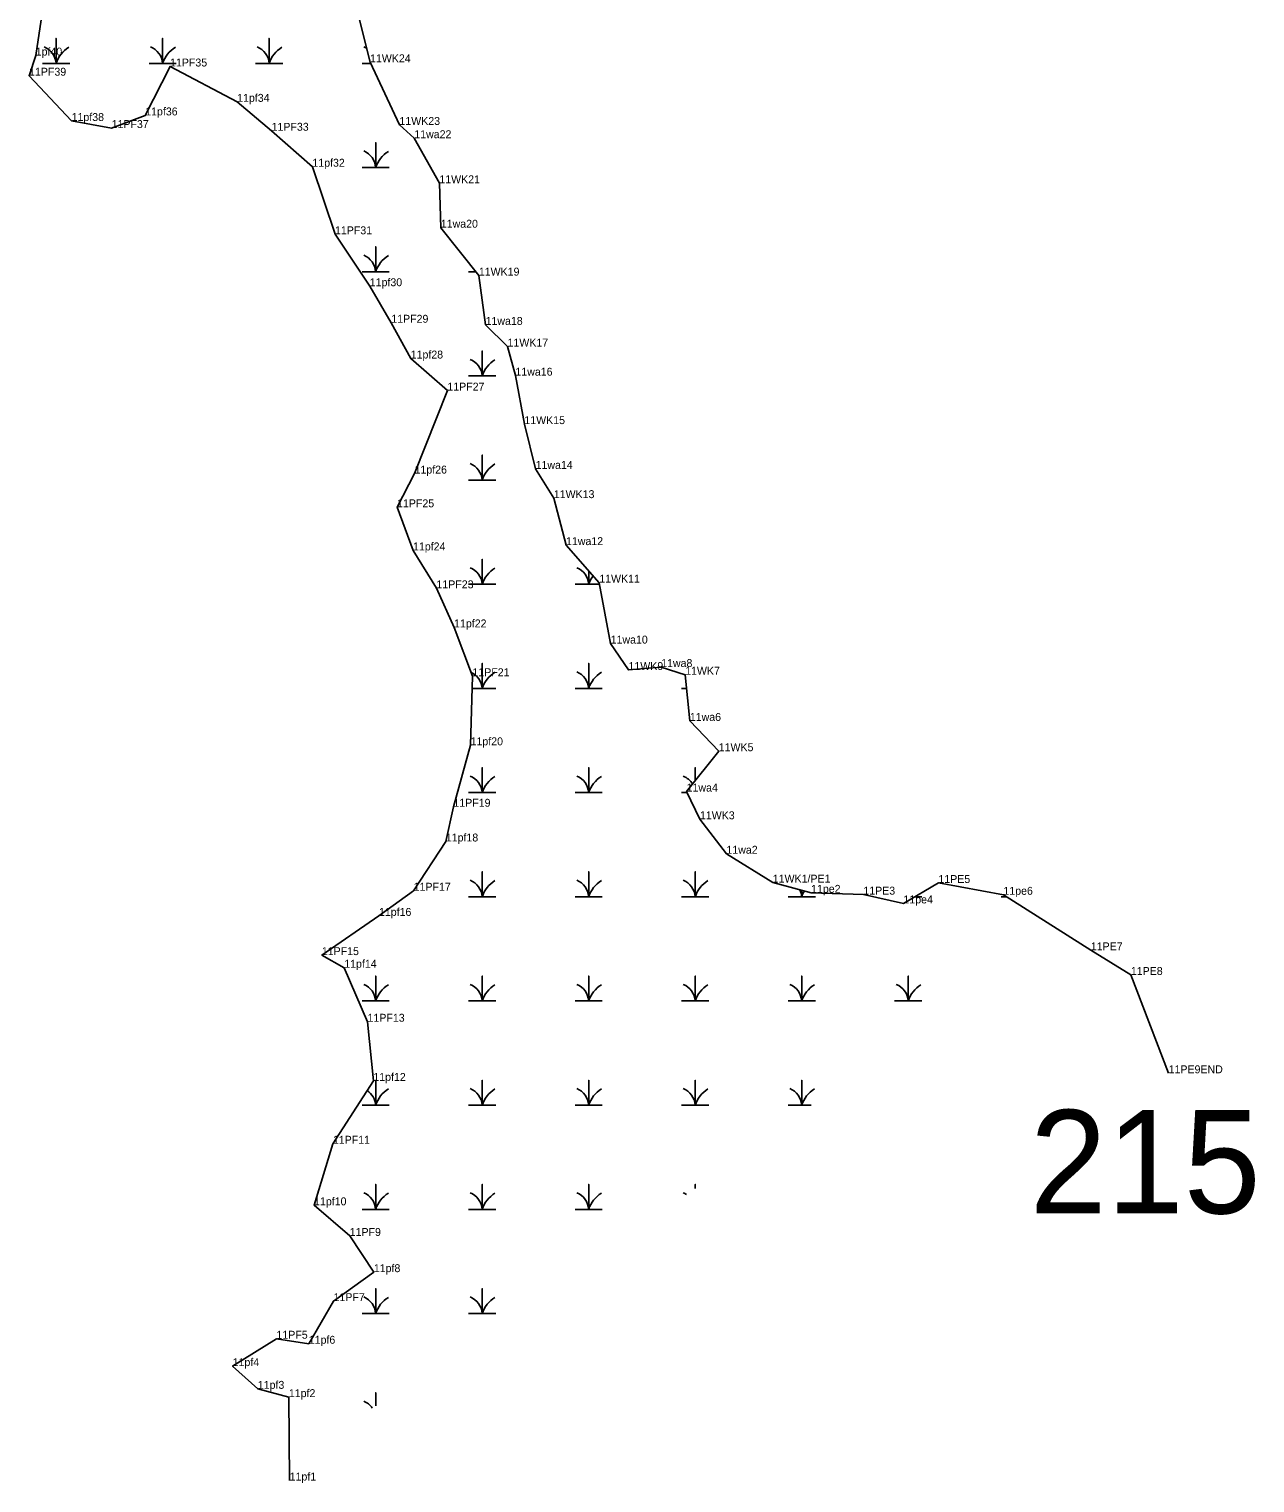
# Model space of a CAD drawing. Extents: x 2072529 to 2268796, y 436423 to 470397.
# Drawn here: x 2234819 to 2235593, y 448079 to 448997 of the extents above; entities that cross this region are included whole.
import ezdxf

# ---------------------------------------------------------------- set-up
doc = ezdxf.new("R2010")
doc.units = 0
for name, color, linetype in [('Default', 7, 'Continuous'), ('Exist Environmental Wetland Boundary', 7, 'Continuous'), ('Exist Environmental Wetland Boundary Cogo Comment', 7, 'Continuous'), ('Exist Environmental Wetland Boundary Cogo Point CELL', 7, 'Continuous'), ('Exist Hydro Swamp or Marsh', 7, 'Continuous')]:
    doc.layers.add(name, color=color, linetype=linetype)

msp = doc.modelspace()

# ---------------------------------------------------------------- linework, layer by layer
at = {"layer": 'Exist Environmental Wetland Boundary'}
for points in [[(2235024.3, 449016.68), (2235034.29, 448976.24)], [(2234983.52, 448080.45), (2234983.04, 448133.13), (2234963.42, 448138.38), (2234947.54, 448152.71), (2234975.2, 448170.02), (2234995.61, 448166.86), (2235011.24, 448193.78), (2235036.68, 448212.07), (2235021.44, 448234.93), (2234998.95, 448254.29), (2235010.83, 448293.18), (2235036.36, 448332.86), (2235032.71, 448370.24), (2235017.99, 448404.35), (2235003.85, 448412.32), (2235039.92, 448437.08), (2235061.81, 448452.98), (2235082.13, 448484.09), (2235086.92, 448506.04), (2235097.77, 448544.83), (2235098.94, 448588.49), (2235087.36, 448619.32), (2235076.21, 448644.01), (2235061.42, 448667.94), (2235051.35, 448695.16), (2235062.4, 448716.48), (2235083.09, 448768.88), (2235059.95, 448789.14), (2235047.7, 448811.73), (2235034.11, 448834.81), (2235012.16, 448867.6), (2234997.88, 448910.29), (2234972.11, 448933), (2234950.38, 448951.27), (2234908.02, 448973.6), (2234892.34, 448942.69), (2234871.13, 448934.72), (2234845.86, 448939.16), (2234819.01, 448967.79), (2234823.2, 448980.5), (2234826.7, 449003.12)], [(2235034.29, 448976.24), (2235052.84, 448936.68), (2235062.23, 448928.31), (2235078.04, 448899.81), (2235078.97, 448871.77), (2235102.97, 448841.5), (2235107.23, 448810.38), (2235121.09, 448796.7), (2235126.08, 448778.31), (2235131.73, 448747.72), (2235138.81, 448719.4), (2235150.32, 448700.95), (2235158.01, 448671.28), (2235179.01, 448647.56), (2235186.19, 448609.09), (2235197.46, 448592.4), (2235218.09, 448594.26), (2235233.25, 448589.41), (2235236.19, 448560.23), (2235254.42, 448541.12), (2235234.17, 448515.62), (2235242.57, 448498.12), (2235259.31, 448476.34), (2235288.56, 448458.11), (2235312.75, 448451.67), (2235345.74, 448450.52), (2235371.06, 448444.98), (2235393.14, 448457.87), (2235434.17, 448450.43), (2235489.36, 448415.34), (2235514.65, 448399.78), (2235538.49, 448337.67)]]:
    msp.add_lwpolyline(points, dxfattribs=at)
at = {"layer": 'Exist Environmental Wetland Boundary Cogo Point CELL'}
for p, q in [((2234823.2, 448980.5), (2234823.2, 448980.5)), ((2235034.29, 448976.24), (2235034.29, 448976.24)), ((2234819.01, 448967.79), (2234819.01, 448967.79)), ((2234908.02, 448973.6), (2234908.02, 448973.6)), ((2234950.38, 448951.27), (2234950.38, 448951.27)), ((2234845.86, 448939.16), (2234845.86, 448939.16)), ((2234892.34, 448942.69), (2234892.34, 448942.69)), ((2234871.13, 448934.72), (2234871.13, 448934.72)), ((2234972.11, 448933), (2234972.11, 448933)), ((2235052.84, 448936.68), (2235052.84, 448936.68)), ((2235062.23, 448928.31), (2235062.23, 448928.31)), ((2234997.88, 448910.29), (2234997.88, 448910.29)), ((2235078.04, 448899.81), (2235078.04, 448899.81)), ((2235012.16, 448867.6), (2235012.16, 448867.6)), ((2235078.97, 448871.77), (2235078.97, 448871.77)), ((2235102.97, 448841.5), (2235102.97, 448841.5)), ((2235034.11, 448834.81), (2235034.11, 448834.81)), ((2235047.7, 448811.73), (2235047.7, 448811.73)), ((2235107.23, 448810.38), (2235107.23, 448810.38)), ((2235121.09, 448796.7), (2235121.09, 448796.7)), ((2235059.95, 448789.14), (2235059.95, 448789.14)), ((2235126.08, 448778.31), (2235126.08, 448778.31)), ((2235083.09, 448768.88), (2235083.09, 448768.88)), ((2235131.73, 448747.72), (2235131.73, 448747.72)), ((2235138.81, 448719.4), (2235138.81, 448719.4)), ((2235062.4, 448716.48), (2235062.4, 448716.48)), ((2235150.32, 448700.95), (2235150.32, 448700.95)), ((2235051.35, 448695.16), (2235051.35, 448695.16)), ((2235061.42, 448667.94), (2235061.42, 448667.94)), ((2235158.01, 448671.28), (2235158.01, 448671.28)), ((2235076.21, 448644.01), (2235076.21, 448644.01)), ((2235179.01, 448647.56), (2235179.01, 448647.56)), ((2235087.36, 448619.32), (2235087.36, 448619.32)), ((2235186.19, 448609.09), (2235186.19, 448609.09)), ((2235197.46, 448592.4), (2235197.46, 448592.4)), ((2235218.09, 448594.26), (2235218.09, 448594.26)), ((2235233.25, 448589.41), (2235233.25, 448589.41)), ((2235098.94, 448588.49), (2235098.94, 448588.49)), ((2235236.19, 448560.23), (2235236.19, 448560.23)), ((2235097.77, 448544.83), (2235097.77, 448544.83)), ((2235254.42, 448541.12), (2235254.42, 448541.12)), ((2235234.17, 448515.62), (2235234.17, 448515.62)), ((2235086.92, 448506.04), (2235086.92, 448506.04)), ((2235242.57, 448498.12), (2235242.57, 448498.12)), ((2235082.13, 448484.09), (2235082.13, 448484.09)), ((2235259.31, 448476.34), (2235259.31, 448476.34)), ((2235061.81, 448452.98), (2235061.81, 448452.98)), ((2235288.56, 448458.11), (2235288.56, 448458.11)), ((2235312.75, 448451.67), (2235312.75, 448451.67)), ((2235393.14, 448457.87), (2235393.14, 448457.87)), ((2235345.74, 448450.52), (2235345.74, 448450.52)), ((2235371.06, 448444.98), (2235371.06, 448444.98)), ((2235434.17, 448450.43), (2235434.17, 448450.43)), ((2235039.92, 448437.08), (2235039.92, 448437.08)), ((2235489.36, 448415.34), (2235489.36, 448415.34)), ((2235003.85, 448412.32), (2235003.85, 448412.32)), ((2235017.99, 448404.35), (2235017.99, 448404.35)), ((2235514.65, 448399.78), (2235514.65, 448399.78)), ((2235032.71, 448370.24), (2235032.71, 448370.24)), ((2235036.36, 448332.86), (2235036.36, 448332.86)), ((2235538.49, 448337.67), (2235538.49, 448337.67)), ((2235010.83, 448293.18), (2235010.83, 448293.18)), ((2234998.95, 448254.29), (2234998.95, 448254.29)), ((2235021.44, 448234.93), (2235021.44, 448234.93)), ((2235036.68, 448212.07), (2235036.68, 448212.07)), ((2235011.24, 448193.78), (2235011.24, 448193.78)), ((2234975.2, 448170.02), (2234975.2, 448170.02)), ((2234995.61, 448166.86), (2234995.61, 448166.86)), ((2234947.54, 448152.71), (2234947.54, 448152.71)), ((2234963.42, 448138.38), (2234963.42, 448138.38)), ((2234983.04, 448133.13), (2234983.04, 448133.13)), ((2234983.52, 448080.45), (2234983.52, 448080.45))]:
    msp.add_line(p, q, dxfattribs=at)
at = {"layer": 'Exist Hydro Swamp or Marsh'}
for points in [[(2234827.48, 448975.54), (2234836.08, 448975.54), (2234836.08, 448991.32), (2234836.08, 448975.54), (2234844.68, 448975.54)], [(2234894.73, 448975.54), (2234903.33, 448975.54), (2234903.33, 448991.32), (2234903.33, 448975.54), (2234911.93, 448975.54)], [(2234961.98, 448975.54), (2234970.58, 448975.54), (2234970.58, 448991.32), (2234970.58, 448975.54), (2234979.18, 448975.54)], [(2235029.23, 448975.54), (2235034.62, 448975.54)], [(2235029.23, 448909.74), (2235037.83, 448909.74), (2235037.83, 448925.52), (2235037.83, 448909.74), (2235046.43, 448909.74)], [(2235029.23, 448843.94), (2235037.83, 448843.94), (2235037.83, 448859.72), (2235037.83, 448843.94), (2235046.43, 448843.94)], [(2235096.48, 448843.94), (2235101.04, 448843.94)], [(2235096.48, 448778.14), (2235105.08, 448778.14), (2235105.08, 448793.92), (2235105.08, 448778.14), (2235113.68, 448778.14)], [(2235096.48, 448712.34), (2235105.08, 448712.34), (2235105.08, 448728.12), (2235105.08, 448712.34), (2235113.68, 448712.34)], [(2235096.48, 448646.54), (2235105.08, 448646.54), (2235105.08, 448662.32), (2235105.08, 448646.54), (2235113.68, 448646.54)], [(2235163.73, 448646.54), (2235172.33, 448646.54), (2235172.33, 448655.11)], [(2235172.33, 448655.11), (2235172.33, 448646.54), (2235179.2, 448646.54)], [(2235098.73, 448580.74), (2235105.08, 448580.74), (2235105.08, 448596.52), (2235105.08, 448580.74), (2235113.68, 448580.74)], [(2235163.73, 448580.74), (2235172.33, 448580.74), (2235172.33, 448596.52), (2235172.33, 448580.74), (2235180.93, 448580.74)], [(2235230.98, 448580.74), (2235234.12, 448580.74)], [(2235096.48, 448514.94), (2235105.08, 448514.94), (2235105.08, 448530.72), (2235105.08, 448514.94), (2235113.68, 448514.94)], [(2235163.73, 448514.94), (2235172.33, 448514.94), (2235172.33, 448530.72), (2235172.33, 448514.94), (2235180.93, 448514.94)], [(2235239.58, 448522.44), (2235239.58, 448530.72), (2235239.58, 448522.44)], [(2235230.98, 448514.94), (2235234.5, 448514.94)], [(2235096.48, 448449.14), (2235105.08, 448449.14), (2235105.08, 448464.92), (2235105.08, 448449.14), (2235113.68, 448449.14)], [(2235163.73, 448449.14), (2235172.33, 448449.14), (2235172.33, 448464.92), (2235172.33, 448449.14), (2235180.93, 448449.14)], [(2235230.98, 448449.14), (2235239.58, 448449.14), (2235239.58, 448464.92), (2235239.58, 448449.14), (2235248.18, 448449.14)], [(2235298.23, 448449.14), (2235306.83, 448449.14), (2235306.83, 448453.25)], [(2235306.83, 448453.25), (2235306.83, 448449.14), (2235315.43, 448449.14)], [(2235378.19, 448449.14), (2235382.68, 448449.14)], [(2235432.73, 448449.14), (2235436.21, 448449.14)], [(2235029.23, 448383.34), (2235037.83, 448383.34), (2235037.83, 448399.12), (2235037.83, 448383.34), (2235046.43, 448383.34)], [(2235096.48, 448383.34), (2235105.08, 448383.34), (2235105.08, 448399.12), (2235105.08, 448383.34), (2235113.68, 448383.34)], [(2235163.73, 448383.34), (2235172.33, 448383.34), (2235172.33, 448399.12), (2235172.33, 448383.34), (2235180.93, 448383.34)], [(2235230.98, 448383.34), (2235239.58, 448383.34), (2235239.58, 448399.12), (2235239.58, 448383.34), (2235248.18, 448383.34)], [(2235298.23, 448383.34), (2235306.83, 448383.34), (2235306.83, 448399.12), (2235306.83, 448383.34), (2235315.43, 448383.34)], [(2235365.48, 448383.34), (2235374.08, 448383.34), (2235374.08, 448399.12), (2235374.08, 448383.34), (2235382.68, 448383.34)], [(2235029.23, 448317.54), (2235037.83, 448317.54), (2235037.83, 448333.32), (2235037.83, 448317.54), (2235046.43, 448317.54)], [(2235096.48, 448317.54), (2235105.08, 448317.54), (2235105.08, 448333.32), (2235105.08, 448317.54), (2235113.68, 448317.54)], [(2235163.73, 448317.54), (2235172.33, 448317.54), (2235172.33, 448333.32), (2235172.33, 448317.54), (2235180.93, 448317.54)], [(2235230.98, 448317.54), (2235239.58, 448317.54), (2235239.58, 448333.32), (2235239.58, 448317.54), (2235248.18, 448317.54)], [(2235298.23, 448317.54), (2235306.83, 448317.54), (2235306.83, 448333.32), (2235306.83, 448317.54), (2235312.89, 448317.54)], [(2235029.23, 448251.74), (2235037.83, 448251.74), (2235037.83, 448267.52), (2235037.83, 448251.74), (2235046.43, 448251.74)], [(2235096.48, 448251.74), (2235105.08, 448251.74), (2235105.08, 448267.52), (2235105.08, 448251.74), (2235113.68, 448251.74)], [(2235163.73, 448251.74), (2235172.33, 448251.74), (2235172.33, 448267.52), (2235172.33, 448251.74), (2235180.93, 448251.74)], [(2235239.58, 448264.96), (2235239.58, 448267.52), (2235239.58, 448264.96)], [(2235029.23, 448185.94), (2235037.83, 448185.94), (2235037.83, 448201.72), (2235037.83, 448185.94), (2235046.43, 448185.94)], [(2235096.48, 448185.94), (2235105.08, 448185.94), (2235105.08, 448201.72), (2235105.08, 448185.94), (2235113.68, 448185.94)], [(2235037.83, 448127.56), (2235037.83, 448135.92), (2235037.83, 448127.56)]]:
    msp.add_lwpolyline(points, dxfattribs=at)
for centre, radius, start, end in [((2234823.81, 448974.65), 12.3, 4.14034, 67.53497), ((2234854.32, 448969.48), 19.22, 122.12745, 161.62219), ((2234891.06, 448974.65), 12.3, 4.14034, 67.53497), ((2234921.57, 448969.48), 19.22, 122.12745, 161.62219), ((2234958.31, 448974.65), 12.3, 4.14034, 67.53497), ((2234988.82, 448969.48), 19.22, 122.12745, 161.62219), ((2235025.56, 448974.65), 12.3, 57.85137, 67.53497), ((2235025.56, 448908.85), 12.3, 4.14034, 67.53497), ((2235056.07, 448903.68), 19.22, 122.12745, 161.62219), ((2235025.56, 448843.05), 12.3, 4.14034, 67.53497), ((2235056.07, 448837.88), 19.22, 122.12745, 161.62219), ((2235092.81, 448777.25), 12.3, 4.14034, 67.53497), ((2235123.32, 448772.08), 19.22, 122.12745, 161.62219), ((2235092.81, 448711.45), 12.3, 4.14034, 67.53497), ((2235123.32, 448706.28), 19.22, 122.12745, 161.62219), ((2235092.81, 448645.65), 12.3, 4.14034, 67.53497), ((2235123.32, 448640.48), 19.22, 122.12745, 161.62219), ((2235160.06, 448645.65), 12.3, 4.14034, 67.53497), ((2235190.57, 448640.48), 19.22, 143.41853, 161.62219), ((2235092.81, 448579.85), 12.3, 4.14034, 65.08849), ((2235123.32, 448574.68), 19.22, 122.12745, 161.62219), ((2235160.06, 448579.85), 12.3, 4.14034, 67.53497), ((2235190.57, 448574.68), 19.22, 122.12745, 161.62219), ((2235092.81, 448514.05), 12.3, 4.14034, 67.53497), ((2235123.32, 448508.88), 19.22, 122.12745, 161.62219), ((2235160.06, 448514.05), 12.3, 4.14034, 67.53497), ((2235190.57, 448508.88), 19.22, 122.12745, 161.62219), ((2235227.31, 448514.05), 12.3, 30.62936, 67.53497), ((2235092.81, 448448.25), 12.3, 4.14034, 67.53497), ((2235123.32, 448443.08), 19.22, 122.12745, 161.62219), ((2235160.06, 448448.25), 12.3, 4.14034, 67.53497), ((2235190.57, 448443.08), 19.22, 122.12745, 161.62219), ((2235227.31, 448448.25), 12.3, 4.14034, 67.53497), ((2235257.82, 448443.08), 19.22, 122.12745, 161.62219), ((2235294.56, 448448.25), 12.3, 4.14034, 25.54441), ((2235325.07, 448443.08), 19.22, 149.61486, 161.62219), ((2235025.56, 448382.45), 12.3, 4.14034, 67.53497), ((2235056.07, 448377.28), 19.22, 122.12745, 161.62219), ((2235092.81, 448382.45), 12.3, 4.14034, 67.53497), ((2235123.32, 448377.28), 19.22, 122.12745, 161.62219), ((2235160.06, 448382.45), 12.3, 4.14034, 67.53497), ((2235190.57, 448377.28), 19.22, 122.12745, 161.62219), ((2235227.31, 448382.45), 12.3, 4.14034, 67.53497), ((2235257.82, 448377.28), 19.22, 122.12745, 161.62219), ((2235294.56, 448382.45), 12.3, 4.14034, 67.53497), ((2235325.07, 448377.28), 19.22, 122.12745, 161.62219), ((2235361.81, 448382.45), 12.3, 4.14034, 67.53497), ((2235392.32, 448377.28), 19.22, 122.12745, 161.62219), ((2235025.56, 448316.65), 12.3, 4.14034, 55.81176), ((2235056.07, 448311.48), 19.22, 122.12745, 161.62219), ((2235092.81, 448316.65), 12.3, 4.14034, 67.53497), ((2235123.32, 448311.48), 19.22, 122.12745, 161.62219), ((2235160.06, 448316.65), 12.3, 4.14034, 67.53497), ((2235190.57, 448311.48), 19.22, 122.12745, 161.62219), ((2235227.31, 448316.65), 12.3, 4.14034, 67.53497), ((2235257.82, 448311.48), 19.22, 122.12745, 161.62219), ((2235294.56, 448316.65), 12.3, 4.14034, 67.53497), ((2235325.07, 448311.48), 19.22, 122.12745, 161.62219), ((2235025.56, 448250.85), 12.3, 4.14034, 67.53497), ((2235056.07, 448245.68), 19.22, 122.12745, 161.62219), ((2235092.81, 448250.85), 12.3, 4.14034, 67.53497), ((2235123.32, 448245.68), 19.22, 122.12745, 161.62219), ((2235160.06, 448250.85), 12.3, 4.14034, 67.53497), ((2235190.57, 448245.68), 19.22, 122.12745, 161.62219), ((2235227.31, 448250.85), 12.3, 56.27543, 67.53497), ((2235025.56, 448185.05), 12.3, 4.14034, 67.53497), ((2235056.07, 448179.88), 19.22, 122.12745, 161.62219), ((2235092.81, 448185.05), 12.3, 4.14034, 67.53497), ((2235123.32, 448179.88), 19.22, 122.12745, 161.62219), ((2235025.56, 448119.25), 12.3, 34.32541, 67.53497)]:
    msp.add_arc(centre, radius, start, end, dxfattribs=at)

# ---------------------------------------------------------------- texts
at = {"layer": 'Default'}
msp.add_text('215', height=65.34, dxfattribs=at).set_placement((2235450.85, 448249.14))
at = {"layer": 'Exist Environmental Wetland Boundary Cogo Comment'}
for s, p in [('1pf40', (2234823.2, 448980.5)), ('11PF35', (2234908.02, 448973.6)), ('11WK24', (2235034.29, 448976.24)), ('11PF39', (2234819.01, 448967.79)), ('11pf34', (2234950.38, 448951.27)), ('11pf36', (2234892.34, 448942.69)), ('11pf38', (2234845.86, 448939.16)), ('11PF37', (2234871.13, 448934.72)), ('11PF33', (2234972.11, 448933)), ('11WK23', (2235052.84, 448936.68)), ('11wa22', (2235062.23, 448928.31)), ('11pf32', (2234997.88, 448910.29)), ('11WK21', (2235078.04, 448899.81)), ('11wa20', (2235078.97, 448871.77)), ('11PF31', (2235012.16, 448867.6)), ('11WK19', (2235102.97, 448841.5)), ('11pf30', (2235034.11, 448834.81)), ('11PF29', (2235047.7, 448811.73)), ('11wa18', (2235107.23, 448810.38)), ('11WK17', (2235121.09, 448796.7)), ('11pf28', (2235059.95, 448789.14)), ('11wa16', (2235126.08, 448778.31)), ('11PF27', (2235083.09, 448768.88)), ('11WK15', (2235131.73, 448747.72)), ('11pf26', (2235062.4, 448716.48)), ('11wa14', (2235138.81, 448719.4)), ('11PF25', (2235051.35, 448695.16)), ('11WK13', (2235150.32, 448700.95)), ('11pf24', (2235061.42, 448667.94)), ('11wa12', (2235158.01, 448671.28)), ('11PF23', (2235076.21, 448644.01)), ('11WK11', (2235179.01, 448647.56)), ('11pf22', (2235087.36, 448619.32)), ('11wa10', (2235186.19, 448609.09)), ('11wa8', (2235218.09, 448594.26)), ('11PF21', (2235098.94, 448588.49)), ('11WK9', (2235197.46, 448592.4)), ('11WK7', (2235233.25, 448589.41)), ('11wa6', (2235236.19, 448560.23)), ('11pf20', (2235097.77, 448544.83)), ('11WK5', (2235254.42, 448541.12)), ('11wa4', (2235234.17, 448515.62)), ('11PF19', (2235086.92, 448506.04)), ('11WK3', (2235242.57, 448498.12)), ('11pf18', (2235082.13, 448484.09)), ('11wa2', (2235259.31, 448476.34)), ('11WK1/PE1', (2235288.56, 448458.11)), ('11PE5', (2235393.14, 448457.87)), ('11PF17', (2235061.81, 448452.98)), ('11pe2', (2235312.75, 448451.67)), ('11PE3', (2235345.74, 448450.52)), ('11pe6', (2235434.17, 448450.43)), ('11pf16', (2235039.92, 448437.08)), ('11pe4', (2235371.06, 448444.98)), ('11PF15', (2235003.85, 448412.32)), ('11PE7', (2235489.36, 448415.34)), ('11pf14', (2235017.99, 448404.35)), ('11PE8', (2235514.65, 448399.78)), ('11PF13', (2235032.71, 448370.24)), ('11PE9END', (2235538.49, 448337.67)), ('11pf12', (2235036.36, 448332.86)), ('11PF11', (2235010.83, 448293.18)), ('11pf10', (2234998.95, 448254.29)), ('11PF9', (2235021.44, 448234.93)), ('11pf8', (2235036.68, 448212.07)), ('11PF7', (2235011.24, 448193.78)), ('11PF5', (2234975.2, 448170.02)), ('11pf6', (2234995.61, 448166.86)), ('11pf4', (2234947.54, 448152.71)), ('11pf3', (2234963.42, 448138.38)), ('11pf2', (2234983.04, 448133.13)), ('11pf1', (2234983.52, 448080.45))]:
    msp.add_text(s, height=5, dxfattribs=at).set_placement(p)

doc.saveas('drawing.dxf')
